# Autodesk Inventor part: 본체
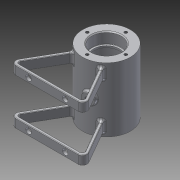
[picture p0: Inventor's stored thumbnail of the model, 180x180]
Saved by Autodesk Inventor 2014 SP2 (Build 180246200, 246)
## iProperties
Created: 2016-03
Part Number: 본체
Material: 알루미늄 6061
Document SubType Name: Modeling
Designer: 이도윤
Density: 2.71 g/cm^3
Appearance: 알루미늄 - 평지
Mass: 213.314 g
Surface Area: 333.8 cm^2
Volume: 78.7135 cm^3
Author: 이도윤
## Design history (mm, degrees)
sketch "스케치1"
  geometry: C1 r 26 at (0, 65); 1 further point
  constraints: 1 centre point, 1 vertical alignment
  dimensions: "d1" = 52 diameter of C1; "d2" = 65 distance of point (0, 0) C1.centre
extrude "돌출1" new body sketch "스케치1" distance "d3" = 70; taper "d4" = 0 deg
sketch "스케치2"
  geometry: C1 r 26 at (0, 0) reference; C2 r 16 at (0, 0); 1 further point
  constraints: 1 centre point, 1 coincident
  dimensions: "d5" = 32 diameter of C2
extrude "돌출2" cut sketch "스케치2" distance "d6" = 12; taper "d7" = 0 deg
sketch "스케치4"
  geometry: C1 r 16 at (0, 0) reference; C2 r 14 at (0, 0); 1 further point
  constraints: 1 centre point, 1 coincident
  dimensions: "d11" = 28 diameter of C2
extrude "돌출4" cut sketch "스케치4" distance "d12" = 2; taper "d13" = 0 deg
sketch "스케치5"
  geometry: C1 r 14 at (0, 0) reference; C2 r 21 at (0, 0); 1 further point
  constraints: 1 centre point, 1 coincident
  dimensions: "d14" = 42 diameter of C2
extrude "돌출5" cut sketch "스케치5" distance "d15" = 42; taper "d16" = 0 deg
sketch "스케치6"
  geometry: C1 r 26 at (0, 0) reference; C2 r 16 at (0, 0); 1 further point
  constraints: 1 centre point, 1 coincident
  dimensions: "d17" = 32 diameter of C2
extrude "돌출6" cut sketch "스케치6" distance "d18" = 12; taper "d19" = 0 deg
sketch "스케치7"
  geometry: C1 r 16 at (0, 0) reference; C2 r 14 at (0, 0); 1 further point
  constraints: 1 centre point, 1 coincident
  dimensions: "d20" = 28 diameter of C2
extrude "돌출7" cut sketch "스케치7" distance "d21" = 2; taper "d22" = 0 deg
node "작업 평면1"
sketch "스케치8"
  geometry: L1 (0, 63.034)-(0, -112.363); L2 (16.613, -20)-(42.594, -65); L3 (42.594, -65)-(-42.594, -65); L4 (-42.594, -65)-(-16.613, -20); L5 (-37.398, -62)-(-14.183, -21.791); L6 (-37.398, -62)-(37.398, -62); L7 (37.398, -62)-(14.183, -21.791); A1 r 26 centre (0, 0) between (16.613, -20) and (-16.613, -20) reference; A2 r 26 centre (0, 0) between (-16.613, -20) and (-14.183, -21.791); A3 r 26 centre (0, 0) between (0, -26) and (16.613, -20); 2 further points
  constraints: 14 end point, 7 point on circle, 3 parallel, 2 centre point, 2 coincident, 2 point on line, 1 midpoint, 1 perpendicular, 1 vertical, 1 vertical alignment
  dimensions: "d24" = 30 deg angle of L1 L2; "d25" = 30 deg angle of L1 L4; "d26" = 45 distance from line of L3 L2.start; "d27" = 3 distance between parallel lines of L4 L5; "d28" = 3 distance between parallel lines of L3 L6; "d29" = 3 distance between parallel lines of L2 L7
extrude "돌출8" join sketch "스케치8" distance "d32" = 10; taper "d33" = 0 deg
node "작업 평면2"
sketch "스케치9"
  geometry: C1 r 26 at (0, 0) reference; A1 r 21 centre (0, 0) between (0, 21) and (21, 0); 3 further points
  constraints: 4 point on circle, 1 centre point, 1 coincident
  dimensions: "d35" = 42 diameter of A1; "d36" = 42 distance of point (0, -21) A1.start; "d37" = 42 distance of A1.end point (-21, 0); "d38" = 21 horizontal distance of point (-21, 0) A1.start; "d39" = 21 horizontal distance of point (0, -21) point (-21, 0)
hole "구멍1" sketch "스케치9" at (0, 21), (21, 0), (0, -21), (-21, 0) diameter "d40" = 3.242; stored, may be unused: countersink angle "d44" = 90 deg, drill point angle "d46" = 118 deg; dims "d41" = 8, "d42" = 4, "d43" = 2, "d45" = 10
node "작업 평면4"
sketch "스케치10"
  geometry: L1 (26, 70)-(-26, 70) reference; L2 (26, 0)-(26, 70) reference; L3 (-26, 0)-(26, 0) reference; L4 (16.613, 5)-(16.613, 15) reference; L5 (16.613, 15)-(14.183, 15) reference; L6 (14.183, 15)-(14.183, 5) reference; L7 (14.183, 5)-(16.613, 5) reference; L8 (-16.613, 15)-(-16.613, 5) reference; L9 (-16.613, 5)-(-14.183, 5) reference; L10 (-14.183, 5)-(-14.183, 15) reference; L11 (-14.183, 15)-(-16.613, 15) reference; L12 (16.613, 55)-(16.613, 65) reference; L13 (16.613, 65)-(14.183, 65) reference; L14 (14.183, 65)-(14.183, 55) reference; L15 (14.183, 55)-(16.613, 55) reference; L16 (-16.613, 65)-(-16.613, 55) reference; L17 (-16.613, 55)-(-14.183, 55) reference; L18 (-14.183, 55)-(-14.183, 65) reference; L19 (-14.183, 65)-(-16.613, 65) reference; L20 (26, 70)-(-26, 70) reference; L21 (-26, 0)-(26, 0) reference; L22 (-26, 0)-(-26, 70) reference; C1 r 5 at (0, 35); 2 further points
  constraints: 1 centre point, 1 coincident
  dimensions: "d49" = 10 diameter of C1
extrude "돌출9" join sketch "스케치10" stored distance "d50" = 10; taper "d51" = 0 deg
sketch "스케치11"
  geometry: L1 (0, 42.85)-(0, -85.589); L2 (0, 0)-(24.51, -91.474); L3 (7.506, -28.012)-(13.301, -26.459); L4 (13.301, -26.459)-(12.343, -22.883); A1 r 26 centre (0, 0) between (6.729, -25.114) and (12.343, -22.883); 1 further point
  constraints: 8 end point, 2 perpendicular, 2 point on circle, 2 point on line, 1 centre point, 1 coincident, 1 vertical, 3 other
  dimensions: "d52" = 15 deg angle of L1 L2; "d53" = 6 distance of L3.start L3.end; "d54" = 29 distance of L3.start L2.start
revolve "회전1" sketch "스케치11" stored, may be unused: angle "d55" = 90 deg
sketch "스케치12"
  geometry: C1 r 5 at (0, 0) reference; 2 further points
  constraints: 1 coincident
hole "구멍2" sketch "스케치12" at (0, 0) diameter "d56" = 5.188; stored, may be unused: countersink angle "d60" = 90 deg, drill point angle "d62" = 0 deg; dims "d57" = 9, "d58" = 4, "d59" = 2, "d61" = 9
sketch "스케치13"
  geometry: C1 r 6 at (0, 0) reference; 2 further points
  constraints: 1 coincident
hole "구멍3" sketch "스케치13" at (0, 0) diameter "d63" = 5.188; stored, may be unused: countersink angle "d67" = 90 deg, drill point angle "d69" = 0 deg; dims "d64" = 9, "d65" = 4, "d66" = 2, "d68" = 9
sketch "스케치14"
  geometry: L1 (0, 10)-(74.796, 10) reference; L2 (0, 0)-(0, 10) reference; L3 (37.398, 78.286)-(37.398, -37.071); C1 r 3 at (17.398, 5); C2 r 3 at (57.398, 5); 1 further point
  constraints: 2 centre point, 2 end point, 1 parallel
  dimensions: "d70" = 6 diameter of C1; "d71" = 6 diameter of C2; "d72" = 40 distance of C1.centre C2.centre; "d73" = 20 horizontal distance of point (37.398, 65) C1.centre; "d74" = 5 distance from line of L1 C1.centre; "d75" = 5 distance from line of L1 C2.centre
extrude "돌출10" cut sketch "스케치14" stored distance "d76" = 10; taper "d77" = 0 deg
fillet "모깎기2" dims "d79" = 3
fillet "모깎기3" dims "d80" = 0.3
chamfer "모따기1" distance "d81" = 1; stored, may be unused: second distance "d82" = 2, angle "d83" = 45 deg
fillet "모깎기4" dims "d84" = 2
fillet "모깎기5" dims "d85" = 2
fillet "모깎기6" dims "d86" = 5
fillet "모깎기7" dims "d87" = 5
fillet "모깎기8" dims "d88" = 2.5
fillet "모깎기10" dims "d90" = 0.5
fillet "모깎기11" dims "d91" = 0.5
node "작업 평면7"
sketch "스케치16"
  geometry: L1 (19.407, 14.066)-(19.407, 55.934); L2 (19.407, 55.934)-(-19.407, 55.934); L3 (-19.407, 55.934)-(-19.407, 14.066); L4 (-19.407, 14.066)-(19.407, 14.066); L5 (-29, 30)-(-29, 40) reference; L6 (-26, 0)-(26, 0) reference; L7 (-26, 0)-(-26, 70) reference; 3 further points
  constraints: 2 midpoint, 2 other
  dimensions: "d92" = 26 distance from line of L7 point (0, 14.066); "d93" = 35 distance from line of L6 point (19.407, 35)
feature "엠보싱1" sketch "스케치16" dims "d1" = 52, "d2" = 65, "d94" = 0.5, "d95" = 0
fillet "모깎기12" dims "d96" = 3
node "솔리드1"
mirror "대칭1"
mirror "대칭2"
mirror "대칭3"
node "작업 평면3"
node "투영된 루프1"
node "작업 평면5"
node "작업 평면6"
other parameters: "d23" = -5, "d34" = -35, "d47" = 94
